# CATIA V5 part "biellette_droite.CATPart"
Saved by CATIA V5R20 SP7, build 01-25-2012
Part number: biellette_droite
Bounding box of the stored display mesh (mm): x 38.796 to 229.954, y 597.426 to 729.954, z -20 to 0
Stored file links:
  U:\IAO\thinkmotion catia2\biellette_droite.CATPart
  U:\IAO\thinkmotion catia2\Ass_862_adubourgno.CATProduct
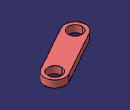
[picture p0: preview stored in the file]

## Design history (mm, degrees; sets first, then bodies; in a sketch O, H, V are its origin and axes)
Set1
  Plane1: linked copy from another document
  Point1 "B": linked copy from another document
  Point2 "F": linked copy from another document
Body1 (main body)
  Sketch1 on Plane1, origin (0, 0, 0), H (1, 0, 0), V (0, 1, 0)
    axis line L1 (68.75, 627.38) -> (200, 700)
    point P1 (68.75, 627.38)
    point P2 (200, 700)
    reference projected point E2 (68.75, 627.38) from Point1
    reference projected point E3 (200, 700) from Point2
    arc A1 centre (68.75, 627.38) radius 30 from (54.2261, 653.6299) to (83.2739, 601.1301) ccw
    point P3 (68.75, 627.38)
    reference projected point E4 (68.75, 627.38) from Point1
    arc A2 centre (200, 700) radius 30 from (214.5239, 673.7501) to (185.4761, 726.2499) ccw
    point P4 (200, 700)
    reference projected point E5 (200, 700) from Point2
    line L2 (185.4761, 726.2499) -> (54.2261, 653.6299)
    point P5 (54.2261, 653.6299)
    point P6 (185.4761, 726.2499)
    line L3 (83.2739, 601.1301) -> (214.5239, 673.7501)
    reference projected point E6 (68.75, 627.38) from Point1
    reference projected point E7 (200, 700) from Point2
    circle A3 centre (68.75, 627.38) radius 20
    point P9 (68.75, 627.38)
    reference projected point E8 (68.75, 627.38) from Point1
    circle A4 centre (200, 700) radius 20
    point P10 (200, 700)
    reference projected point E9 (200, 700) from Point2
    distance E2 P1 = 0
    distance E3 P2 = 0
    radius A1 = 30
    distance E4 P3 = 0
    radius A2 = 30
    distance E5 P4 = 0
    distance L2 L1 = 30
    distance L3 L1 = 30
    distance E6 P5 = 30
    distance E7 P6 = 30
    radius A3 = 20
    distance E8 P9 = 0
    radius A4 = 20
    distance E9 P10 = 0
  Pad1: profile Sketch1, direction (0, 0, -1), length 20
